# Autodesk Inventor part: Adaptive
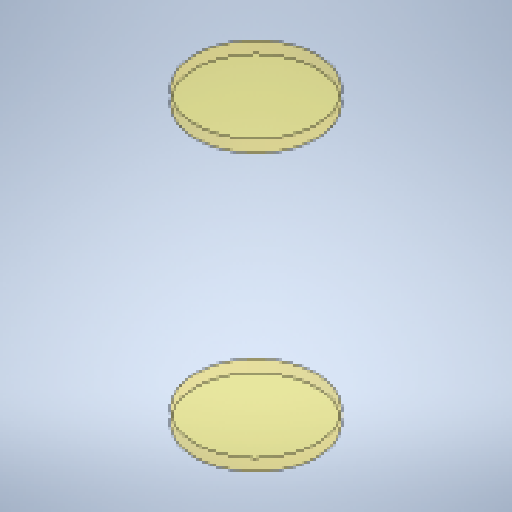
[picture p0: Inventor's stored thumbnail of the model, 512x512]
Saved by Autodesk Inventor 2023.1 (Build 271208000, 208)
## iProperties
Created: 2022-08
Part Number: Adaptive
Material: Generic
Document SubType Name: Modeling
Designer: milos
Density: 1 g/cm^3
Appearance: Default
Author: milos
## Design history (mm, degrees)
feature "Composite1"
body "Srf1"
